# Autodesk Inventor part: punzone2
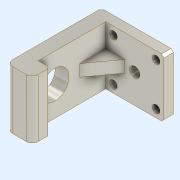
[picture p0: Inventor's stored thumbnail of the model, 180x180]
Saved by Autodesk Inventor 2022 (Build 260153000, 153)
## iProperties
Created: 2022-01
Part Number: punzone2
Material: Generico
Document SubType Name: Modeling
Designer: admin
Density: 1 g/cm^3
Appearance: Titanio - Lucidato
Author: admin
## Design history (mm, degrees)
sketch "Schizzo1"
  geometry: L1 (23.086, 24.5)-(24.5, 23.086) reference; L2 (-23.086, 24.5)-(23.086, 24.5) reference; L3 (-24.5, 23.086)-(-23.086, 24.5) reference; L4 (-24.5, -23.086)-(-24.5, 23.086) reference; L5 (-23.086, -24.5)-(-24.5, -23.086) reference; L6 (23.086, -24.5)-(-23.086, -24.5) reference; L7 (24.5, -23.086)-(23.086, -24.5) reference; L8 (24.5, 23.086)-(24.5, -23.086) reference; L9 (-24.5, 23.086)-(-24.5, 24.5); L10 (-24.5, 24.5)-(-23.086, 24.5); L11 (-24.5, 24.5)-(24.5, 24.5); L12 (24.5, 24.5)-(24.5, -24.5); L13 (24.5, -24.5)-(-24.5, -24.5); L14 (-24.5, -24.5)-(-24.5, 24.5); C1 r 4.323 at (0, 0) reference; C2 r 3.25 at (-18, -18) reference; C3 r 3.25 at (-18, 18) reference; C4 r 3.25 at (18, -18) reference; C5 r 3.25 at (18, 18) reference; 7 further points
  constraints: 12 end point, 3 perpendicular, 2 parallel, 1 horizontal, 1 point on line
  node "Riferimento1"
node "Piano di lavoro1"
extrude "Estrusione1" new body sketch "Schizzo1" distance "d0" = 8; taper "d1" = 0 deg
sketch "Schizzo4"
  geometry: L1 (24.5, -24.5)-(36.11, -24.5); L2 (36.11, -24.5)-(36.11, 24.5); L3 (36.11, 24.5)-(24.5, 24.5); L4 (24.5, 24.5)-(24.5, -24.5); 1 further point
  constraints: 8 end point, 2 parallel, 1 horizontal, 1 perpendicular
  dimensions: "d4" = 11.61 distance of L1.start L1.end
extrude "Estrusione2" join sketch "Schizzo4" distance "d2" = 80; taper "d3" = 0 deg
chamfer "Smusso1" distance "d5" = 2; stored, may be unused: second distance "d6" = 2, angle "d7" = 45 deg
node "Piano di lavoro2"
sketch "Schizzo5"
  geometry: L1 (-28.823, 8)-(-20.176, 8) reference; L2 (-33, 8)-(-49, 30); L3 (-49, 8)-(-49, 30); L4 (-49, 8)-(-33, 8); 1 further point
  constraints: 6 end point, 1 perpendicular, 1 point on line, 1 vertical
  dimensions: "d14" = 16 distance of L3.start L2.start; "d25" = 22 distance of L3.start L2.end
extrude "Estrusione3" join sketch "Schizzo5" stored distance "d8" = 10; taper "d9" = 0 deg
fillet "Raccordo1" dims "d10" = 5
chamfer "Smusso3" distance "d15" = 2; stored, may be unused: second distance "d16" = 2, angle "d17" = 45 deg
sketch "Schizzo6"
  geometry: L1 (0, 0)-(0, 49) reference; L2 (72, 0)-(0, 0) reference; L3 (0, 49)-(15, 49); L4 (15, 49)-(15, 0); L5 (15, 0)-(0, 0); L6 (0, 0)-(0, 49); 1 further point
  constraints: 8 end point, 2 parallel, 1 horizontal, 1 perpendicular, 1 point on line
  dimensions: "d18" = 15 distance of L4.end L5.end
extrude "Estrusione4" join sketch "Schizzo6" distance "d19" = 10; taper "d20" = 0 deg
fillet "Raccordo2" dims "d21" = 5
chamfer "Smusso4" distance "d22" = 2; stored, may be unused: second distance "d23" = 2, angle "d24" = 45 deg
sketch "Schizzo7"
  geometry: L1 (-22, 19.5)-(-22, 29.5) reference; L2 (-22, 24.5)-(-40.715, 24.5); C1 r 12 at (-43, 24.5); 1 further point
  constraints: 2 end point, 1 centre point, 1 horizontal, 1 midpoint, 1 point on line
  dimensions: "d26" = 24 diameter of C1; "d27" = 21 distance from line of L1 C1.centre
extrude "Estrusione5" cut sketch "Schizzo7" extent not by distance; stored distance "d28" = 0; taper "d29" = 0 deg
node "Solido1"
